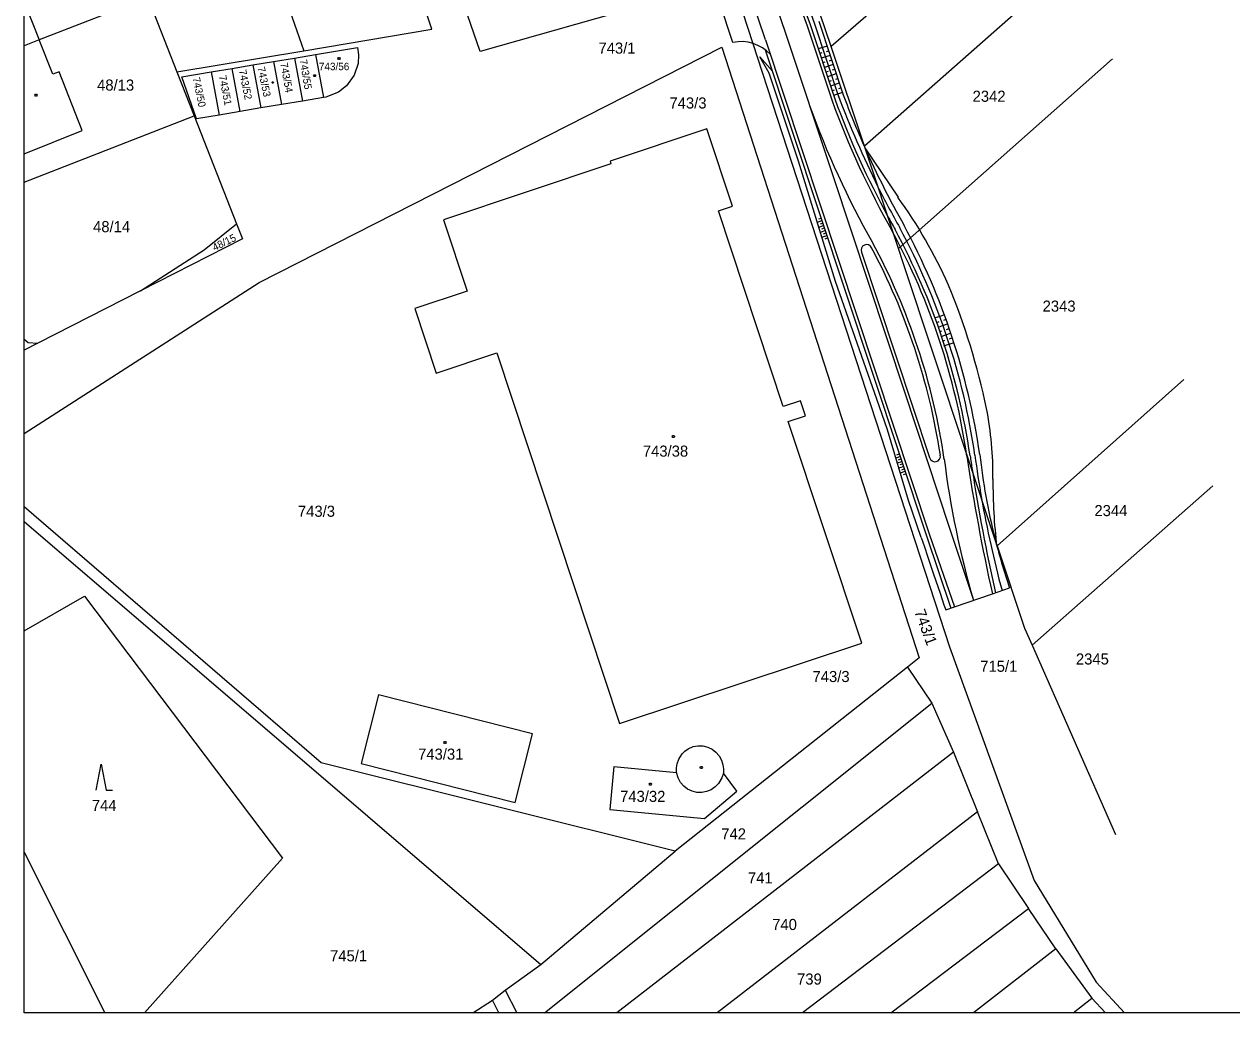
# Model space of a CAD drawing. Extents: x -639590 to -639298, y -1193269 to -1192863.
# Drawn here: x -639590.4 to -639405.1, y -1193268.8 to -1193117.1 of the extents above; entities that cross this region are included whole.
import ezdxf

# ---------------------------------------------------------------- set-up
doc = ezdxf.new("R2010")
doc.units = 0
for name, color, linetype in [('Vrstva 1', 7, 'Continuous'), ('Vrstva 19', 7, 'Continuous'), ('Vrstva 2', 7, 'Continuous'), ('Vrstva 21', 7, 'Continuous'), ('Vrstva 3', 7, 'Continuous'), ('Vrstva 4', 7, 'Continuous'), ('Vrstva 5', 7, 'Continuous'), ('Vrstva 61', 7, 'Continuous')]:
    doc.layers.add(name, color=color, linetype=linetype)

msp = doc.modelspace()

# ---------------------------------------------------------------- linework, layer by layer
at = {"layer": 'Vrstva 1'}
for p, q in [((-639377.41, -1193043.16), (-639466.59, -1193120.49)), ((-639413.94, -1193093.82), (-639461.48, -1193135.8)), ((-639527.84, -1193117.84), (-639534.22, -1193098.9)), ((-639520.42, -1193121.23), (-639528.59, -1193097.82)), ((-639486.01, -1193097.33), (-639448.4, -1193212.6)), ((-639466.59, -1193120.49), (-639474.06, -1193098.11)), ((-639554.24, -1193101.82), (-639547.48, -1193121.13)), ((-639483.53, -1193110.77), (-639520.42, -1193121.23)), ((-639571.44, -1193112.95), (-639588.08, -1193119.47)), ((-639571.44, -1193112.95), (-639566.95, -1193124.39)), ((-639590.23, -1193114.05), (-639588.08, -1193119.47)), ((-639588.08, -1193119.47), (-639590.39, -1193120.38)), ((-639585.99, -1193124.74), (-639588.08, -1193119.47)), ((-639547.48, -1193121.13), (-639527.84, -1193117.84)), ((-639566.95, -1193124.39), (-639547.48, -1193121.13)), ((-639554.34, -1193156.7), (-639483.37, -1193120.58)), ((-639545.71, -1193121.71), (-639539.23, -1193120.63)), ((-639539.23, -1193120.63), (-639539.09, -1193121.76)), ((-639483.37, -1193120.58), (-639453.06, -1193214.27)), ((-639461.48, -1193135.8), (-639466.59, -1193120.49)), ((-639555.29, -1193123.31), (-639552.12, -1193122.78)), ((-639552.12, -1193122.78), (-639548.91, -1193122.25)), ((-639552.12, -1193122.78), (-639550.89, -1193129.39)), ((-639548.91, -1193122.25), (-639545.71, -1193121.71)), ((-639548.91, -1193122.25), (-639547.69, -1193128.85)), ((-639545.71, -1193121.71), (-639544.48, -1193128.31)), ((-639539.16, -1193123.08), (-639539.76, -1193124.9)), ((-639539.09, -1193121.76), (-639539.16, -1193123.08)), ((-639423.4, -1193122.38), (-639456.25, -1193151.46)), ((-639585, -1193124.36), (-639585.99, -1193124.74)), ((-639581.47, -1193133.39), (-639585, -1193124.36)), ((-639566.95, -1193124.39), (-639564.32, -1193131.1)), ((-639566.22, -1193125.14), (-639561.7, -1193124.39)), ((-639561.7, -1193124.39), (-639558.5, -1193123.85)), ((-639561.7, -1193124.39), (-639560.48, -1193131)), ((-639558.5, -1193123.85), (-639555.29, -1193123.31)), ((-639557.27, -1193130.46), (-639558.5, -1193123.85)), ((-639555.29, -1193123.31), (-639554.07, -1193129.92)), ((-639539.76, -1193124.9), (-639540.92, -1193126.5)), ((-639563.93, -1193131.58), (-639566.22, -1193125.14)), ((-639540.92, -1193126.5), (-639542.16, -1193127.49)), ((-639544.48, -1193128.31), (-639547.69, -1193128.85)), ((-639544.1, -1193128.25), (-639544.48, -1193128.31)), ((-639542.16, -1193127.49), (-639544.1, -1193128.25)), ((-639557.27, -1193130.46), (-639560.48, -1193131)), ((-639554.07, -1193129.92), (-639557.27, -1193130.46)), ((-639550.89, -1193129.39), (-639554.07, -1193129.92)), ((-639547.69, -1193128.85), (-639550.89, -1193129.39)), ((-639590.39, -1193141.32), (-639564.32, -1193131.1)), ((-639564.32, -1193131.1), (-639557.8, -1193147.72)), ((-639560.48, -1193131), (-639563.93, -1193131.58)), ((-639590.39, -1193136.94), (-639581.47, -1193133.39)), ((-639485.63, -1193133.13), (-639500.51, -1193138.07)), ((-639481.7, -1193144.98), (-639485.63, -1193133.13)), ((-639456.25, -1193151.46), (-639461.48, -1193135.8)), ((-639500.37, -1193138.49), (-639526.08, -1193147.06)), ((-639500.51, -1193138.07), (-639500.37, -1193138.49)), ((-639483.88, -1193145.7), (-639481.7, -1193144.98)), ((-639526.08, -1193147.06), (-639522.43, -1193158.01)), ((-639473.92, -1193175.75), (-639483.88, -1193145.7)), ((-639562.77, -1193151.67), (-639557.8, -1193147.72)), ((-639557.8, -1193147.72), (-639556.9, -1193150.01)), ((-639556.9, -1193150.01), (-639572.53, -1193157.99)), ((-639572.53, -1193157.99), (-639562.77, -1193151.67)), ((-639455.57, -1193153.51), (-639456.25, -1193151.46)), ((-639441.09, -1193197.09), (-639455.57, -1193153.51)), ((-639590.39, -1193179.89), (-639554.34, -1193156.7)), ((-639572.53, -1193157.99), (-639588.28, -1193166.02)), ((-639522.43, -1193158.01), (-639530.44, -1193160.7)), ((-639530.44, -1193160.7), (-639527.19, -1193170.59)), ((-639590.39, -1193165.4), (-639589.78, -1193165.93)), ((-639588.28, -1193166.02), (-639590.39, -1193167.1)), ((-639589.78, -1193165.93), (-639588.28, -1193166.02)), ((-639527.19, -1193170.59), (-639517.87, -1193167.48)), ((-639517.87, -1193167.48), (-639499.04, -1193224.37)), ((-639412.49, -1193171.58), (-639441.09, -1193197.09)), ((-639471.27, -1193174.87), (-639473.92, -1193175.75)), ((-639470.51, -1193177.15), (-639471.27, -1193174.87)), ((-639473.17, -1193178.03), (-639470.51, -1193177.15)), ((-639461.88, -1193212.05), (-639473.17, -1193178.03)), ((-639435.74, -1193212.36), (-639408.03, -1193187.88)), ((-639544.82, -1193230.4), (-639590.39, -1193191.14)), ((-639590.39, -1193193.39), (-639511.13, -1193261.36)), ((-639441.09, -1193197.09), (-639436.9, -1193209.72)), ((-639590.39, -1193210.13), (-639581.12, -1193204.81)), ((-639581.12, -1193204.81), (-639550.73, -1193245.01)), ((-639436.9, -1193209.72), (-639435.74, -1193212.36)), ((-639499.04, -1193224.37), (-639461.88, -1193212.05)), ((-639448.4, -1193212.6), (-639435.44, -1193248.47)), ((-639435.74, -1193212.36), (-639422.96, -1193241.4)), ((-639454.87, -1193215.71), (-639490.49, -1193243.94)), ((-639453.06, -1193214.27), (-639454.87, -1193215.71)), ((-639454.87, -1193215.71), (-639451.12, -1193221.27)), ((-639536.05, -1193219.98), (-639538.68, -1193230.5)), ((-639512.42, -1193225.96), (-639536.05, -1193219.98)), ((-639510.58, -1193268.77), (-639451.12, -1193221.27)), ((-639451.12, -1193221.27), (-639447.8, -1193228.76)), ((-639515.08, -1193236.47), (-639512.42, -1193225.96)), ((-639447.8, -1193228.76), (-639499.44, -1193268.77)), ((-639489.45, -1193229.01), (-639489.04, -1193228.6)), ((-639489.04, -1193228.6), (-639488.51, -1193228.26)), ((-639488.51, -1193228.26), (-639487.75, -1193227.92)), ((-639487.75, -1193227.92), (-639487.01, -1193227.78)), ((-639487.01, -1193227.78), (-639486.26, -1193227.8)), ((-639486.26, -1193227.8), (-639485.52, -1193227.98)), ((-639485.52, -1193227.98), (-639484.84, -1193228.3)), ((-639484.84, -1193228.3), (-639484.25, -1193228.75)), ((-639484.25, -1193228.75), (-639483.76, -1193229.33)), ((-639447.8, -1193228.76), (-639444.12, -1193237.92)), ((-639490.49, -1193243.94), (-639544.82, -1193230.4)), ((-639538.68, -1193230.5), (-639515.08, -1193236.47)), ((-639490.31, -1193231.18), (-639490.22, -1193230.54)), ((-639490.22, -1193230.54), (-639489.97, -1193229.83)), ((-639489.97, -1193229.83), (-639489.45, -1193229.01)), ((-639483.76, -1193229.33), (-639483.4, -1193229.99)), ((-639483.4, -1193229.99), (-639483.18, -1193230.71)), ((-639499.92, -1193230.97), (-639500.54, -1193237.59)), ((-639499.92, -1193230.97), (-639490.31, -1193231.87)), ((-639490.31, -1193231.87), (-639490.31, -1193231.18)), ((-639483.18, -1193230.71), (-639483.12, -1193231.32)), ((-639483.12, -1193231.32), (-639483.12, -1193231.98)), ((-639481.04, -1193234.75), (-639483.12, -1193231.98)), ((-639486.01, -1193238.95), (-639481.04, -1193234.75)), ((-639500.54, -1193237.59), (-639486.01, -1193238.95)), ((-639444.12, -1193237.92), (-639484.06, -1193268.77)), ((-639440.91, -1193245.9), (-639444.12, -1193237.92)), ((-639590.39, -1193244.13), (-639578, -1193268.77)), ((-639550.73, -1193245.01), (-639571.95, -1193268.77)), ((-639511.13, -1193261.36), (-639490.49, -1193243.94)), ((-639440.91, -1193245.9), (-639470.97, -1193268.77)), ((-639440.91, -1193245.9), (-639436.28, -1193252.77)), ((-639435.44, -1193248.47), (-639425.91, -1193264.07)), ((-639457.4, -1193268.77), (-639436.28, -1193252.77)), ((-639432.11, -1193258.97), (-639436.28, -1193252.77)), ((-639432.11, -1193258.97), (-639444.72, -1193268.77)), ((-639432.11, -1193258.97), (-639426.57, -1193266.5)), ((-639516.59, -1193265.27), (-639511.13, -1193261.36)), ((-639518.54, -1193266.82), (-639516.59, -1193265.27)), ((-639516.59, -1193265.27), (-639514.8, -1193268.77)), ((-639425.91, -1193264.07), (-639421.55, -1193268.77)), ((-639521.53, -1193268.77), (-639518.54, -1193266.82)), ((-639517.54, -1193268.77), (-639518.54, -1193266.82)), ((-639429.45, -1193268.77), (-639426.57, -1193266.5)), ((-639426.57, -1193266.5), (-639424.5, -1193268.77)), ((-639546.37, -1193268.77), (-639546.37, -1193268.77)), ((-639546.37, -1193268.77), (-639546.37, -1193268.77))]:
    msp.add_line(p, q, dxfattribs=at)
at = {"layer": 'Vrstva 19'}
for p, q in [((-639473.46, -1193108.58), (-639470.27, -1193117.3)), ((-639476.66, -1193119.47), (-639479.62, -1193110.62)), ((-639470.27, -1193117.3), (-639466.5, -1193128.68)), ((-639476.66, -1193119.47), (-639451.5, -1193195.41)), ((-639476.66, -1193119.47), (-639451.5, -1193195.41)), ((-639476.66, -1193119.47), (-639451.5, -1193195.41)), ((-639461.41, -1193136.01), (-639456.32, -1193143.6)), ((-639461.92, -1193152.05), (-639451.48, -1193183.57)), ((-639450.59, -1193162.09), (-639449.88, -1193161.86)), ((-639449.88, -1193161.86), (-639449.16, -1193161.62)), ((-639450.36, -1193162.81), (-639450.02, -1193162.69)), ((-639450.14, -1193163.53), (-639448.71, -1193163.05)), ((-639449.3, -1193162.46), (-639448.94, -1193162.34)), ((-639448.87, -1193163.89), (-639448.5, -1193163.77)), ((-639449.92, -1193164.24), (-639449.58, -1193164.13)), ((-639449.71, -1193164.96), (-639448.28, -1193164.49)), ((-639449.5, -1193165.68), (-639449.14, -1193165.57)), ((-639448.43, -1193165.33), (-639448.07, -1193165.21)), ((-639449.3, -1193166.41), (-639447.87, -1193165.94)), ((-639451.49, -1193195.42), (-639447.68, -1193206.47)), ((-639447.68, -1193206.47), (-639441.85, -1193204.46))]:
    msp.add_line(p, q, dxfattribs=at)
for points in [[(-639476.54, -1193109.6), (-639475.01, -1193114.22), (-639473.58, -1193118.45)], [(-639473.58, -1193118.45), (-639466.34, -1193140.28), (-639455.33, -1193173.5), (-639448.41, -1193194.39), (-639444.75, -1193205.46)]]:
    msp.add_lwpolyline(points, dxfattribs=at)
for centre, radius, start, end in [((-639341.48, -1193083.2), 133.03, 199.9901, 209.5581), ((-639341.48, -1193083.2), 136.53, 199.8349, 209.5581), ((-639331.26, -1193077.97), 142.5, 204.0141, 209.4063), ((-639331.26, -1193077.97), 143.25, 206.555, 209.4063), ((-639518.48, -1193188.24), 76.52, 24.0138, 35.6872), ((-639341.48, -1193083.2), 132.53, 208.5789, 209.5581), ((-639548.66, -1193198.29), 103.98, 8.2542, 28.4057), ((-639548.66, -1193198.29), 104.47, 8.254, 28.4117), ((-639548.68, -1193198.29), 105.25, 8.2553, 28.362), ((-639548.68, -1193198.29), 106, 8.2553, 28.362), ((-639461.14, -1193151.73), 0.847, 24.1804, 202.5056), ((-639548.68, -1193198.29), 100.5, 8.2553, 28.362), ((-639548.68, -1193198.29), 100, 8.6913, 27.9766), ((-639548.68, -1193198.29), 108.25, 11.8582, 22.3675), ((-639492.88, -1193186.04), 51.12, 359.0898, 11.2724), ((-639450.66, -1193183.36), 0.847, 194.1623, 12.4876), ((-639308.9, -1193166.06), 141.45, 187.1943, 196.1752), ((-639156.33, -1193140.66), 292.56, 188.392, 192.5965), ((-639157.51, -1193140.91), 290.86, 188.3779, 188.7971), ((-639286.01, -1193162.26), 159.89, 187.5155, 189.9241), ((-639350.86, -1193173.03), 93.46, 186.1735, 194.1285), ((-639361.06, -1193187.47), 80.7, 179.56, 186.9423)]:
    msp.add_arc(centre, radius, start, end, dxfattribs=at)
at = {"layer": 'Vrstva 21'}
for p, q in [((-639472.98, -1193108.41), (-639469.8, -1193117.13)), ((-639481.66, -1193119.86), (-639483.73, -1193113.68)), ((-639469.8, -1193117.13), (-639466.03, -1193128.51)), ((-639468.47, -1193116.61), (-639464.73, -1193127.9)), ((-639476.68, -1193121), (-639451.97, -1193195.57)), ((-639476.68, -1193121), (-639451.97, -1193195.57)), ((-639467.21, -1193120.41), (-639468.56, -1193120.86)), ((-639467.3, -1193121.23), (-639466.98, -1193121.13)), ((-639468.01, -1193121.47), (-639468.33, -1193121.57)), ((-639466.74, -1193121.84), (-639468.09, -1193122.29)), ((-639467.54, -1193122.89), (-639467.85, -1193123)), ((-639466.82, -1193122.66), (-639466.5, -1193122.55)), ((-639466.27, -1193123.26), (-639467.62, -1193123.71)), ((-639467.06, -1193124.32), (-639467.38, -1193124.42)), ((-639465.8, -1193124.69), (-639467.15, -1193125.13)), ((-639466.35, -1193124.08), (-639466.03, -1193123.97)), ((-639466.59, -1193125.74), (-639466.91, -1193125.85)), ((-639465.33, -1193126.11), (-639466.68, -1193126.56)), ((-639465.88, -1193125.5), (-639465.56, -1193125.4)), ((-639465.41, -1193126.93), (-639465.09, -1193126.82)), ((-639466.12, -1193127.16), (-639466.44, -1193127.27)), ((-639464.85, -1193127.53), (-639466.2, -1193127.98)), ((-639468.7, -1193147.43), (-639468.03, -1193147.2)), ((-639468.49, -1193146.93), (-639468.13, -1193146.81)), ((-639468.46, -1193148.19), (-639467.75, -1193147.95)), ((-639468.24, -1193147.7), (-639467.88, -1193147.57)), ((-639468.22, -1193148.96), (-639467.5, -1193148.71)), ((-639467.99, -1193148.46), (-639467.62, -1193148.33)), ((-639467.74, -1193149.22), (-639467.37, -1193149.09)), ((-639467.99, -1193149.72), (-639467.25, -1193149.47)), ((-639467.5, -1193149.98), (-639467.12, -1193149.85)), ((-639456.7, -1193183.63), (-639456.03, -1193183.4)), ((-639456.49, -1193183.13), (-639456.13, -1193183.01)), ((-639456.42, -1193184.38), (-639455.76, -1193184.15)), ((-639456.24, -1193183.89), (-639455.88, -1193183.77)), ((-639456.19, -1193185.15), (-639455.5, -1193184.91)), ((-639456, -1193184.65), (-639455.63, -1193184.53)), ((-639455.96, -1193185.91), (-639455.25, -1193185.67)), ((-639455.75, -1193185.42), (-639455.38, -1193185.29)), ((-639455.5, -1193186.18), (-639455.12, -1193186.05)), ((-639451.97, -1193195.57), (-639448.24, -1193206.67)), ((-639441.85, -1193204.46), (-639439.2, -1193203.55)), ((-639449, -1193206.93), (-639447.68, -1193206.47))]:
    msp.add_line(p, q, dxfattribs=at)
for points in [[(-639472.28, -1193108.17), (-639472.14, -1193108.53), (-639469.18, -1193116.87), (-639465.39, -1193128.31)], [(-639452.77, -1193195.84), (-639454.69, -1193190.16), (-639457.94, -1193179.31), (-639459.59, -1193174.59), (-639465.89, -1193156.53), (-639471.58, -1193138.08), (-639476.11, -1193124.57), (-639477.5, -1193122.07), (-639475.6, -1193124.27)], [(-639452.77, -1193195.84), (-639452.28, -1193197.27), (-639451.8, -1193198.69), (-639450.86, -1193201.45), (-639449.86, -1193204.39), (-639449.27, -1193206.14), (-639449, -1193206.93)]]:
    msp.add_lwpolyline(points, dxfattribs=at)
for centre, radius, start, end in [((-639480.4, -1193125.79), 6.06, 42.2, 101.9643), ((-639341.48, -1193083.2), 132.53, 199.9932, 208.5789), ((-639331.26, -1193077.97), 143.25, 200.418, 206.555), ((-639331.26, -1193077.97), 142.5, 200.5124, 204.0141), ((-639157.51, -1193140.91), 290.86, 188.7971, 192.5885), ((-639286.01, -1193162.26), 159.89, 189.9241, 195.1157), ((-639350.86, -1193173.03), 93.46, 194.1285, 199.0564)]:
    msp.add_arc(centre, radius, start, end, dxfattribs=at)
at = {"layer": 'Vrstva 3'}
msp.add_lwpolyline([(-639579.32, -1193234.62), (-639578.57, -1193230.62), (-639577.82, -1193234.62), (-639576.82, -1193234.62)], dxfattribs=at)
at = {"layer": 'Vrstva 4'}
for p, q in [((-639490.05, -1193232.73), (-639490.31, -1193231.87)), ((-639483.12, -1193231.98), (-639483.36, -1193232.69)), ((-639489.68, -1193233.41), (-639490.05, -1193232.73)), ((-639489.19, -1193233.99), (-639489.68, -1193233.41)), ((-639488.6, -1193234.44), (-639489.19, -1193233.99)), ((-639484.38, -1193234.1), (-639485, -1193234.53)), ((-639483.86, -1193233.56), (-639484.38, -1193234.1)), ((-639483.36, -1193232.69), (-639483.86, -1193233.56)), ((-639487.92, -1193234.77), (-639488.6, -1193234.44)), ((-639487.18, -1193234.94), (-639487.92, -1193234.77)), ((-639486.43, -1193234.96), (-639487.18, -1193234.94)), ((-639485.69, -1193234.82), (-639486.43, -1193234.96)), ((-639485, -1193234.53), (-639485.69, -1193234.82))]:
    msp.add_line(p, q, dxfattribs=at)
at = {"layer": 'Vrstva 5'}
for points in [[(-639542, -1193122.18), (-639541.91, -1193122.33), (-639542, -1193122.48), (-639542.18, -1193122.48), (-639542.27, -1193122.33), (-639542.18, -1193122.18)], [(-639545.73, -1193124.81), (-639545.64, -1193124.96), (-639545.73, -1193125.11), (-639545.91, -1193125.11), (-639546, -1193124.96), (-639545.91, -1193124.81)], [(-639552.19, -1193125.91), (-639552.13, -1193126.01), (-639552.19, -1193126.11), (-639552.31, -1193126.11), (-639552.37, -1193126.01), (-639552.31, -1193125.91)], [(-639588.48, -1193127.8), (-639588.39, -1193127.95), (-639588.48, -1193128.1), (-639588.66, -1193128.1), (-639588.75, -1193127.95), (-639588.66, -1193127.8)], [(-639490.68, -1193180.2), (-639490.59, -1193180.35), (-639490.68, -1193180.5), (-639490.86, -1193180.5), (-639490.95, -1193180.35), (-639490.86, -1193180.2)], [(-639525.74, -1193227.15), (-639525.65, -1193227.3), (-639525.74, -1193227.45), (-639525.92, -1193227.45), (-639526.01, -1193227.3), (-639525.92, -1193227.15)], [(-639486.42, -1193230.98), (-639486.33, -1193231.13), (-639486.42, -1193231.28), (-639486.6, -1193231.28), (-639486.69, -1193231.13), (-639486.6, -1193230.98)], [(-639494.22, -1193233.54), (-639494.13, -1193233.69), (-639494.22, -1193233.84), (-639494.4, -1193233.84), (-639494.49, -1193233.69), (-639494.4, -1193233.54)]]:
    msp.add_lwpolyline(points, close=True, dxfattribs=at)
at = {"layer": 'Vrstva 61'}
for points in [[(-639590.39, -1193268.77), (-639590.39, -1192863.27)], [(-639298.39, -1193268.77), (-639590.39, -1193268.77)]]:
    msp.add_lwpolyline(points, dxfattribs=at)

# ---------------------------------------------------------------- texts
at = {"layer": 'Vrstva 2'}
for s, height, p in [('743/1', 1.7, (-639502.28, -1193121.58)), ('743/56', 1.14, (-639545.17, -1193124.12)), ('48/13', 1.7, (-639579.2, -1193127.25)), ('743/3', 1.7, (-639491.39, -1193130)), ('2342', 1.7, (-639444.88, -1193128.97)), ('48/14', 1.7, (-639579.82, -1193148.98)), ('2343', 1.7, (-639434.14, -1193161.17)), ('743/38', 1.7, (-639495.47, -1193183.42)), ('743/3', 1.7, (-639548.39, -1193192.65)), ('2344', 1.7, (-639426.19, -1193192.55)), ('2345', 1.7, (-639429.03, -1193215.32)), ('715/1', 1.7, (-639443.71, -1193216.44)), ('743/3', 1.7, (-639469.44, -1193218.01)), ('743/31', 1.7, (-639529.95, -1193229.92)), ('744', 1.7, (-639580.01, -1193237.79)), ('743/32', 1.7, (-639498.96, -1193236.4)), ('742', 1.7, (-639483.44, -1193242.16)), ('741', 1.7, (-639479.35, -1193248.91)), ('740', 1.7, (-639475.63, -1193256.06)), ('745/1', 1.7, (-639543.46, -1193260.87)), ('739', 1.7, (-639471.81, -1193264.43))]:
    msp.add_text(s, height=height, dxfattribs=at).set_placement(p)
for s, height, rotation, p in [('743/54', 1.14, 280.5201, (-639551.11, -1193123.06)), ('743/55', 1.14, 279.6607, (-639548.14, -1193122.54)), ('743/51', 1.14, 281.0931, (-639560.53, -1193125.02)), ('743/52', 1.14, 281.6088, (-639557.46, -1193124.16)), ('743/53', 1.14, 281.8379, (-639554.6, -1193123.73)), ('743/50', 1.14, 281.8952, (-639564.56, -1193125.32)), ('48/15', 1.14, 26.2988, (-639561.17, -1193151.9)), ('743/1', 1.7, 290.3392, (-639453.84, -1193207.21))]:
    msp.add_text(s, height=height, rotation=rotation, dxfattribs=at).set_placement(p)

doc.saveas('drawing.dxf')
